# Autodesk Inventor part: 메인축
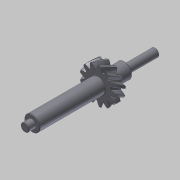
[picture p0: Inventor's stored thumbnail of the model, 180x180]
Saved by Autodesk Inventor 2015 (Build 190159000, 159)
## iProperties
Created: 2018-07
Part Number: 메인축
Material: 강철
Document SubType Name: Modeling
Designer: mduedu
Categories: <?xml version="1.0" encoding="UTF-16"?> <MemberInstance><Categories><FamilyTemplate><FamilyTemplateParameter ValueType="xs:double" Id="1" ObjectReferenceKey="da
Density: 7.85 g/cm^3
Mass: 182.309 g
Surface Area: 79.8926 cm^2
Volume: 23.2241 cm^3
Appearance: 강철
Author: mduedu
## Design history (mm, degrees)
sketch "Sketch1"
  geometry: C1 r 17.232 at (0, 0)
  constraints: 1 centre point
  dimensions: "d0" = 34.46497 diameter of C1 (= da_da)
extrude "Extrusion1" new body sketch "Sketch1" distance "d1" = 10 (= da_b); taper "d2" = 0 deg
workplane "Work Plane2"
sketch "Sketch2"
  geometry: C1 r 17.232 at (0, 0) reference; C2 r 15.087 at (0, 0)
  constraints: 1 centre point, 1 coincident
  dimensions: "d3" = 30.17368 diameter of C2 (= da_dw)
feature "피치 지름" sketch "Sketch2" dims "d4" = 10, "d5" = 0
workplane "Work Plane8"
workplane "Work Plane9"
feature "스퍼 기어" dims "da_b" = 10, "da_d" = 30.02221, "da_aw" = 44.1, "da_da" = 34.46497, "da_df" = 25.47121, "da_dw" = 30.17368, angle "da_beta" = 30 deg, "da_lefttooth" = 0, "da_righttooth" = 10
sketch "스케치3"
  geometry: C1 r 7.5 at (0, 0); 1 further point
  constraints: 1 centre point, 1 coincident
  dimensions: "d49" = 15 diameter of C1
extrude "돌출2" join sketch "스케치3" distance "d50" = 64; taper "d51" = 0 deg
sketch "스케치4"
  geometry: C1 r 4 at (0, 0); 1 further point
  constraints: 1 centre point, 1 coincident
  dimensions: "d52" = 8 diameter of C1
extrude "돌출3" join sketch "스케치4" distance "d53" = 7; taper "d54" = 0 deg
sketch "스케치5"
  geometry: C1 r 7.5 at (0, 0) reference; C2 r 7.5 at (0, 0) reference; 1 further point
extrude "돌출4" join sketch "스케치5" distance "d55" = 16; taper "d56" = 0 deg
sketch "스케치6"
  geometry: C1 r 4 at (0, 0); 1 further point
  constraints: 1 centre point, 1 coincident
  dimensions: "d57" = 8 diameter of C1
extrude "돌출5" join sketch "스케치6" distance "d58" = 30; taper "d59" = 0 deg
chamfer "모따기1" distance "d60" = 0.5; stored, may be unused: second distance "d61" = 2, angle "d62" = 45 deg
fillet "모깎기1" dims "d63" = 0.5
body "Solid1"
body "Srf1"
node "투영된 루프1"
other parameters: "d16" = 44.1 (= da_aw), "d17" = 0, "d34" = 2.41661 (computed from da_z), "d39" = 0, "d41" = 0, "d43" = 44.1 (= da_aw), "d46" = 44.1 (= da_aw), "d47" = 0, "d48" = 0
